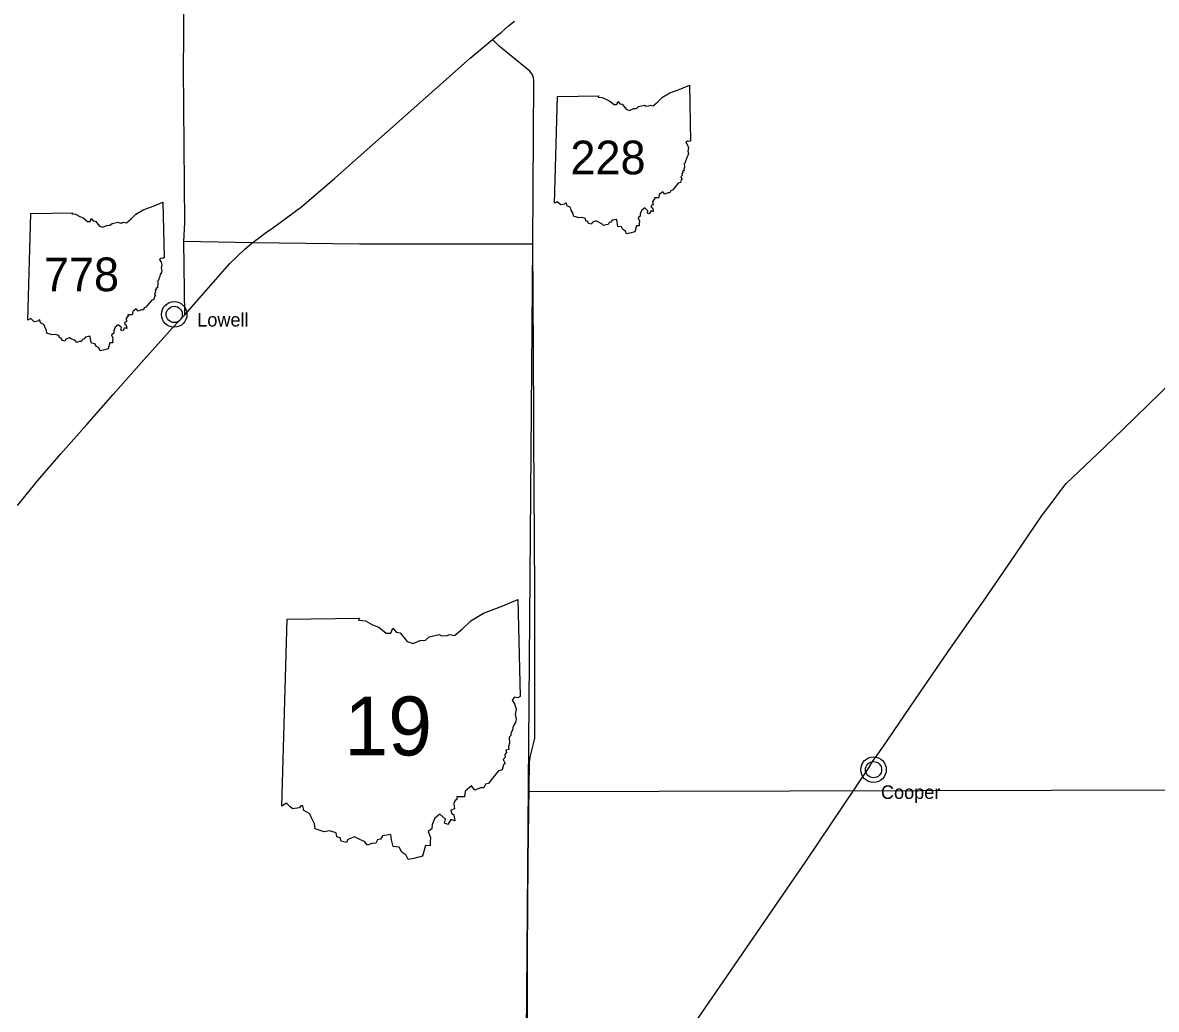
# Model space of a CAD drawing. Extents: x 0 to 882, y 0 to 440.
# Drawn here: x 381 to 468.1, y 237.6 to 313.4 of the extents above; entities that cross this region are included whole.
import ezdxf

# ---------------------------------------------------------------- set-up
doc = ezdxf.new("R2010")
doc.units = 0
for name, color, linetype in [('DV_X_Corp_Line', 7, 'Continuous'), ('GM_X_State_Route', 7, 'Continuous'), ('PV_P_Text', 7, 'Continuous'), ('RD_P_Fence', 7, 'Continuous'), ('SH_Data', 7, 'Continuous')]:
    doc.layers.add(name, color=color, linetype=linetype)

msp = doc.modelspace()

# ---------------------------------------------------------------- linework, layer by layer
at = {"layer": 'DV_X_Corp_Line'}
for centre, radius in [((392.644, 290.982), 0.982), ((392.644, 290.982), 0.623), ((446.38, 256.002), 0.982), ((446.38, 256.002), 0.623)]:
    msp.add_circle(centre, radius, dxfattribs=at)
at = {"layer": 'GM_X_State_Route'}
for points in [[(393.388, 296.583), (393.45, 298.02), (393.358, 309.898), (393.373, 312.282), (393.407, 316.485), (393.437, 322.641), (393.442, 323.16), (393.435, 323.568), (393.418, 329.26), (393.416, 329.793), (393.427, 329.817), (393.429, 329.823)], [(380.594, 276.297), (382.177, 278.219), (383.927, 280.267), (385.929, 282.534), (387.961, 284.83), (390.302, 287.496), (392.516, 289.957), (393.451, 290.953), (396.929, 294.898), (398.065, 296.003), (398.64, 296.481), (399.2, 296.898), (399.758, 297.317), (400.184, 297.613), (402.445, 299.276), (404.992, 301.46), (406.789, 303.043), (412.646, 308.25), (415.387, 310.662), (417.112, 312.1), (417.456, 312.406), (417.755, 312.634), (418.337, 313.152), (418.789, 313.518)], [(420.189, 296.375), (420.264, 308.966), (420.258, 309.159), (420.174, 309.385), (419.979, 309.671), (417.622, 311.587), (417.375, 311.828), (417.112, 312.1)], [(420.189, 296.375), (406.87, 296.372), (398.64, 296.481), (393.388, 296.583)], [(393.451, 290.953), (393.388, 296.583)], [(420.244, 288.037), (420.244, 288.063), (420.189, 296.375)], [(420.287, 281.563), (420.287, 281.596), (420.277, 283.008), (420.244, 288.037)], [(423.359, 222.836), (427.539, 229.077), (432.091, 235.746), (433.123, 237.244), (441.18, 248.941), (446.03, 256.151), (446.362, 256.695), (446.656, 257.106), (447.133, 257.815), (449.995, 261.974), (452.053, 265.013), (454.264, 268.16), (454.833, 268.957), (457.293, 272.533), (459.339, 275.545), (460.095, 276.557), (460.596, 277.229), (461.169, 277.995), (463.596, 280.26), (465.537, 282.134), (471.405, 287.839)], [(420.36, 269.737), (420.287, 281.563)], [(419.612, 222.364), (419.763, 229.03), (419.793, 241.9), (419.851, 249.025), (419.955, 256.517), (419.996, 256.959), (420.244, 257.98), (420.365, 258.414), (420.36, 269.737)]]:
    msp.add_lwpolyline(points, dxfattribs=at)
at = {"layer": 'PV_P_Text'}
for p, q in [((421.864, 299.522), (422.094, 307.729)), ((421.864, 299.522), (422.094, 307.729)), ((381.406, 290.538), (381.636, 298.746)), ((381.406, 290.538), (381.636, 298.746)), ((400.919, 253.198), (401.321, 267.56)), ((400.919, 253.198), (401.321, 267.56))]:
    msp.add_line(p, q, dxfattribs=at)
for points in [[(422.094, 307.729), (425.278, 307.782), (425.228, 307.683), (425.529, 307.662), (425.848, 307.487), (426.118, 307.376), (426.448, 307.115), (426.646, 307.118), (426.729, 307.332), (426.88, 307.167), (427.06, 307.138), (427.37, 306.745), (427.627, 306.66), (427.934, 306.794), (428.163, 306.816), (428.331, 306.95), (428.768, 307.063), (428.889, 306.995), (429.121, 307.009), (429.237, 307.059), (429.439, 307.014), (429.794, 307.313), (430.16, 307.665), (430.722, 307.997), (431.562, 308.311), (432.227, 308.592), (432.323, 304.333)], [(422.094, 307.729), (425.278, 307.782), (425.228, 307.683), (425.529, 307.662), (425.848, 307.487), (426.118, 307.376), (426.448, 307.115), (426.646, 307.118), (426.729, 307.332), (426.88, 307.167), (427.06, 307.138), (427.37, 306.745), (427.627, 306.66), (427.934, 306.794), (428.163, 306.816), (428.331, 306.95), (428.768, 307.063), (428.889, 306.995), (429.121, 307.009), (429.237, 307.059), (429.439, 307.014), (429.794, 307.313), (430.16, 307.665), (430.722, 307.997), (431.562, 308.311), (432.227, 308.592), (432.323, 304.333)], [(432.323, 304.333), (432.224, 304.274), (432.072, 304.302), (431.969, 304.182), (432.096, 303.983), (432.156, 303.772), (432.103, 303.54), (432.155, 303.349), (432.12, 303.189), (432.024, 303.029), (431.991, 302.877), (431.909, 302.717), (431.916, 302.627), (431.838, 302.556), (431.852, 302.29), (431.813, 302.142), (431.827, 302.015), (431.7, 301.982), (431.729, 301.876), (431.649, 301.795), (431.666, 301.655), (431.575, 301.566), (431.664, 301.387), (431.593, 301.331), (431.534, 301.113), (431.372, 301.069), (431.048, 300.672), (430.934, 300.522), (430.806, 300.484), (430.735, 300.33), (430.577, 300.329), (430.338, 300.222), (430.183, 300.406), (429.912, 300.185), (429.881, 299.929), (429.538, 299.937), (429.552, 299.808), (429.475, 299.77), (429.406, 299.64), (429.446, 299.41), (429.286, 299.351), (429.305, 299.218), (429.408, 299.136), (429.454, 298.88), (429.283, 298.932), (429.143, 298.717), (429, 298.767), (429.047, 298.95), (428.804, 299.169), (428.575, 298.993), (428.455, 298.713), (428.454, 298.524), (428.283, 298.409), (428.392, 298.143), (428.372, 297.959), (428.376, 297.784), (428.162, 297.79), (428.032, 297.319)], [(432.323, 304.333), (432.224, 304.274), (432.072, 304.302), (431.969, 304.182), (432.096, 303.983), (432.156, 303.772), (432.103, 303.54), (432.155, 303.349), (432.12, 303.189), (432.024, 303.029), (431.991, 302.877), (431.909, 302.717), (431.916, 302.627), (431.838, 302.556), (431.852, 302.29), (431.813, 302.142), (431.827, 302.015), (431.7, 301.982), (431.729, 301.876), (431.649, 301.795), (431.666, 301.655), (431.575, 301.566), (431.664, 301.387), (431.593, 301.331), (431.534, 301.113), (431.372, 301.069), (431.048, 300.672), (430.934, 300.522), (430.806, 300.484), (430.735, 300.33), (430.577, 300.329), (430.338, 300.222), (430.183, 300.406), (429.912, 300.185), (429.881, 299.929), (429.538, 299.937), (429.552, 299.808), (429.475, 299.77), (429.406, 299.64), (429.446, 299.41), (429.286, 299.351), (429.305, 299.218), (429.408, 299.136), (429.454, 298.88), (429.283, 298.932), (429.143, 298.717), (429, 298.767), (429.047, 298.95), (428.804, 299.169), (428.575, 298.993), (428.455, 298.713), (428.454, 298.524), (428.283, 298.409), (428.392, 298.143), (428.372, 297.959), (428.376, 297.784), (428.162, 297.79), (428.032, 297.319)], [(381.636, 298.746), (384.82, 298.799), (384.77, 298.7), (385.071, 298.679), (385.39, 298.504), (385.66, 298.393), (385.99, 298.132), (386.188, 298.135), (386.271, 298.349), (386.422, 298.184), (386.602, 298.154), (386.912, 297.762), (387.169, 297.676), (387.476, 297.811), (387.705, 297.833), (387.873, 297.966), (388.31, 298.08), (388.432, 298.012), (388.663, 298.026), (388.779, 298.076), (388.981, 298.031), (389.336, 298.329), (389.702, 298.681), (390.264, 299.013), (391.104, 299.328), (391.769, 299.609), (391.865, 295.35)], [(381.636, 298.746), (384.82, 298.799), (384.77, 298.7), (385.071, 298.679), (385.39, 298.504), (385.66, 298.393), (385.99, 298.132), (386.188, 298.135), (386.271, 298.349), (386.422, 298.184), (386.602, 298.154), (386.912, 297.762), (387.169, 297.676), (387.476, 297.811), (387.705, 297.833), (387.873, 297.966), (388.31, 298.08), (388.432, 298.012), (388.663, 298.026), (388.779, 298.076), (388.981, 298.031), (389.336, 298.329), (389.702, 298.681), (390.264, 299.013), (391.104, 299.328), (391.769, 299.609), (391.865, 295.35)], [(428.032, 297.319), (427.661, 297.229), (427.403, 297.175), (427.312, 297.389), (427.127, 297.502), (427.007, 297.718), (426.742, 297.747), (426.68, 298.043), (426.65, 298.283), (426.288, 298.224), (426.188, 298.077), (426.06, 298.037), (425.985, 297.889), (425.81, 297.877), (425.623, 297.807), (425.5, 297.952), (425.192, 298.098), (425.053, 298.173), (424.764, 298.057), (424.702, 297.918), (424.472, 297.979), (424.418, 298.133), (424.278, 298.18), (424.248, 298.343), (423.95, 298.43), (423.722, 298.396), (423.32, 298.527), (423.295, 298.742), (423.158, 299.004), (423.087, 299.186), (422.833, 299.325), (422.781, 299.542), (422.7, 299.535), (422.626, 299.447), (422.344, 299.407), (422.231, 299.496), (422.073, 299.646), (421.864, 299.522)], [(428.032, 297.319), (427.661, 297.229), (427.403, 297.175), (427.312, 297.389), (427.127, 297.502), (427.007, 297.718), (426.742, 297.747), (426.68, 298.043), (426.65, 298.283), (426.288, 298.224), (426.188, 298.077), (426.06, 298.037), (425.985, 297.889), (425.81, 297.877), (425.623, 297.807), (425.5, 297.952), (425.192, 298.098), (425.053, 298.173), (424.764, 298.057), (424.702, 297.918), (424.472, 297.979), (424.418, 298.133), (424.278, 298.18), (424.248, 298.343), (423.95, 298.43), (423.722, 298.396), (423.32, 298.527), (423.295, 298.742), (423.158, 299.004), (423.087, 299.186), (422.833, 299.325), (422.781, 299.542), (422.7, 299.535), (422.626, 299.447), (422.344, 299.407), (422.231, 299.496), (422.073, 299.646), (421.864, 299.522)], [(391.865, 295.35), (391.767, 295.29), (391.614, 295.318), (391.511, 295.199), (391.638, 295), (391.698, 294.789), (391.645, 294.557), (391.698, 294.366), (391.662, 294.205), (391.566, 294.046), (391.533, 293.894), (391.451, 293.734), (391.458, 293.644), (391.38, 293.573), (391.394, 293.307), (391.355, 293.159), (391.369, 293.032), (391.243, 292.998), (391.271, 292.893), (391.191, 292.812), (391.208, 292.672), (391.117, 292.583), (391.206, 292.404), (391.135, 292.348), (391.076, 292.13), (390.914, 292.086), (390.59, 291.689), (390.476, 291.539), (390.348, 291.501), (390.277, 291.347), (390.119, 291.346), (389.88, 291.239), (389.725, 291.423), (389.454, 291.202), (389.423, 290.946), (389.08, 290.954), (389.094, 290.825), (389.017, 290.787), (388.948, 290.657), (388.988, 290.427), (388.828, 290.368), (388.847, 290.234), (388.95, 290.153), (388.996, 289.897), (388.825, 289.949), (388.685, 289.734), (388.542, 289.784), (388.589, 289.967), (388.346, 290.186), (388.117, 290.01), (387.997, 289.729), (387.996, 289.54), (387.825, 289.426), (387.934, 289.159), (387.914, 288.976), (387.918, 288.801), (387.704, 288.807), (387.574, 288.336)], [(391.865, 295.35), (391.767, 295.29), (391.614, 295.318), (391.511, 295.199), (391.638, 295), (391.698, 294.789), (391.645, 294.557), (391.698, 294.366), (391.662, 294.205), (391.566, 294.046), (391.533, 293.894), (391.451, 293.734), (391.458, 293.644), (391.38, 293.573), (391.394, 293.307), (391.355, 293.159), (391.369, 293.032), (391.243, 292.998), (391.271, 292.893), (391.191, 292.812), (391.208, 292.672), (391.117, 292.583), (391.206, 292.404), (391.135, 292.348), (391.076, 292.13), (390.914, 292.086), (390.59, 291.689), (390.476, 291.539), (390.348, 291.501), (390.277, 291.347), (390.119, 291.346), (389.88, 291.239), (389.725, 291.423), (389.454, 291.202), (389.423, 290.946), (389.08, 290.954), (389.094, 290.825), (389.017, 290.787), (388.948, 290.657), (388.988, 290.427), (388.828, 290.368), (388.847, 290.234), (388.95, 290.153), (388.996, 289.897), (388.825, 289.949), (388.685, 289.734), (388.542, 289.784), (388.589, 289.967), (388.346, 290.186), (388.117, 290.01), (387.997, 289.729), (387.996, 289.54), (387.825, 289.426), (387.934, 289.159), (387.914, 288.976), (387.918, 288.801), (387.704, 288.807), (387.574, 288.336)], [(387.574, 288.336), (387.203, 288.246), (386.945, 288.192), (386.854, 288.406), (386.669, 288.519), (386.549, 288.734), (386.284, 288.764), (386.222, 289.06), (386.192, 289.3), (385.83, 289.24), (385.731, 289.094), (385.602, 289.054), (385.528, 288.906), (385.352, 288.894), (385.165, 288.824), (385.042, 288.969), (384.734, 289.115), (384.595, 289.19), (384.306, 289.073), (384.244, 288.935), (384.014, 288.996), (383.96, 289.15), (383.82, 289.196), (383.79, 289.36), (383.492, 289.447), (383.264, 289.412), (382.862, 289.544), (382.837, 289.759), (382.7, 290.021), (382.629, 290.203), (382.375, 290.342), (382.323, 290.558), (382.242, 290.552), (382.168, 290.464), (381.886, 290.424), (381.773, 290.512), (381.615, 290.663), (381.406, 290.538)], [(387.574, 288.336), (387.203, 288.246), (386.945, 288.192), (386.854, 288.406), (386.669, 288.519), (386.549, 288.734), (386.284, 288.764), (386.222, 289.06), (386.192, 289.3), (385.83, 289.24), (385.731, 289.094), (385.602, 289.054), (385.528, 288.906), (385.352, 288.894), (385.165, 288.824), (385.042, 288.969), (384.734, 289.115), (384.595, 289.19), (384.306, 289.073), (384.244, 288.935), (384.014, 288.996), (383.96, 289.15), (383.82, 289.196), (383.79, 289.36), (383.492, 289.447), (383.264, 289.412), (382.862, 289.544), (382.837, 289.759), (382.7, 290.021), (382.629, 290.203), (382.375, 290.342), (382.323, 290.558), (382.242, 290.552), (382.168, 290.464), (381.886, 290.424), (381.773, 290.512), (381.615, 290.663), (381.406, 290.538)], [(401.321, 267.56), (406.893, 267.654), (406.806, 267.48), (407.332, 267.444), (407.891, 267.137), (408.363, 266.944), (408.941, 266.487), (409.287, 266.492), (409.433, 266.866), (409.698, 266.577), (410.012, 266.526), (410.555, 265.838), (411.004, 265.689), (411.541, 265.925), (411.942, 265.964), (412.236, 266.197), (413, 266.396), (413.214, 266.276), (413.618, 266.3), (413.822, 266.389), (414.175, 266.31), (414.797, 266.832), (415.437, 267.448), (416.421, 268.029), (417.891, 268.579), (419.053, 269.072), (419.221, 261.618)], [(401.321, 267.56), (406.893, 267.654), (406.806, 267.48), (407.332, 267.444), (407.891, 267.137), (408.363, 266.944), (408.941, 266.487), (409.287, 266.492), (409.433, 266.866), (409.698, 266.577), (410.012, 266.526), (410.555, 265.838), (411.004, 265.689), (411.541, 265.925), (411.942, 265.964), (412.236, 266.197), (413, 266.396), (413.214, 266.276), (413.618, 266.3), (413.822, 266.389), (414.175, 266.31), (414.797, 266.832), (415.437, 267.448), (416.421, 268.029), (417.891, 268.579), (419.053, 269.072), (419.221, 261.618)], [(419.221, 261.618), (419.05, 261.514), (418.783, 261.563), (418.603, 261.354), (418.825, 261.005), (418.93, 260.637), (418.837, 260.23), (418.929, 259.895), (418.867, 259.615), (418.699, 259.336), (418.641, 259.07), (418.498, 258.79), (418.51, 258.633), (418.374, 258.509), (418.399, 258.042), (418.33, 257.784), (418.353, 257.561), (418.133, 257.503), (418.183, 257.319), (418.043, 257.177), (418.073, 256.932), (417.914, 256.776), (418.068, 256.463), (417.944, 256.364), (417.841, 255.984), (417.558, 255.906), (416.992, 255.211), (416.792, 254.948), (416.567, 254.882), (416.443, 254.612), (416.167, 254.611), (415.748, 254.424), (415.477, 254.746), (415.003, 254.358), (414.949, 253.911), (414.349, 253.925), (414.373, 253.699), (414.239, 253.633), (414.117, 253.406), (414.188, 253.003), (413.907, 252.9), (413.941, 252.666), (414.121, 252.523), (414.201, 252.076), (413.902, 252.166), (413.658, 251.789), (413.407, 251.878), (413.489, 252.197), (413.065, 252.581), (412.663, 252.273), (412.453, 251.782), (412.451, 251.451), (412.152, 251.252), (412.344, 250.784), (412.309, 250.463), (412.314, 250.157), (411.94, 250.168), (411.714, 249.343)], [(419.221, 261.618), (419.05, 261.514), (418.783, 261.563), (418.603, 261.354), (418.825, 261.005), (418.93, 260.637), (418.837, 260.23), (418.929, 259.895), (418.867, 259.615), (418.699, 259.336), (418.641, 259.07), (418.498, 258.79), (418.51, 258.633), (418.374, 258.509), (418.399, 258.042), (418.33, 257.784), (418.353, 257.561), (418.133, 257.503), (418.183, 257.319), (418.043, 257.177), (418.073, 256.932), (417.914, 256.776), (418.068, 256.463), (417.944, 256.364), (417.841, 255.984), (417.558, 255.906), (416.992, 255.211), (416.792, 254.948), (416.567, 254.882), (416.443, 254.612), (416.167, 254.611), (415.748, 254.424), (415.477, 254.746), (415.003, 254.358), (414.949, 253.911), (414.349, 253.925), (414.373, 253.699), (414.239, 253.633), (414.117, 253.406), (414.188, 253.003), (413.907, 252.9), (413.941, 252.666), (414.121, 252.523), (414.201, 252.076), (413.902, 252.166), (413.658, 251.789), (413.407, 251.878), (413.489, 252.197), (413.065, 252.581), (412.663, 252.273), (412.453, 251.782), (412.451, 251.451), (412.152, 251.252), (412.344, 250.784), (412.309, 250.463), (412.314, 250.157), (411.94, 250.168), (411.714, 249.343)], [(411.714, 249.343), (411.063, 249.186), (410.612, 249.091), (410.453, 249.466), (410.13, 249.663), (409.92, 250.041), (409.456, 250.092), (409.347, 250.61), (409.295, 251.03), (408.661, 250.926), (408.487, 250.669), (408.262, 250.6), (408.132, 250.342), (407.825, 250.32), (407.496, 250.198), (407.281, 250.452), (406.742, 250.707), (406.5, 250.838), (405.994, 250.634), (405.886, 250.392), (405.483, 250.499), (405.388, 250.768), (405.144, 250.849), (405.09, 251.135), (404.569, 251.288), (404.17, 251.227), (403.467, 251.457), (403.424, 251.834), (403.184, 252.292), (403.059, 252.611), (402.614, 252.854), (402.524, 253.233), (402.382, 253.221), (402.252, 253.068), (401.758, 252.997), (401.561, 253.152), (401.284, 253.416), (400.919, 253.198)], [(411.714, 249.343), (411.063, 249.186), (410.612, 249.091), (410.453, 249.466), (410.13, 249.663), (409.92, 250.041), (409.456, 250.092), (409.347, 250.61), (409.295, 251.03), (408.661, 250.926), (408.487, 250.669), (408.262, 250.6), (408.132, 250.342), (407.825, 250.32), (407.496, 250.198), (407.281, 250.452), (406.742, 250.707), (406.5, 250.838), (405.994, 250.634), (405.886, 250.392), (405.483, 250.499), (405.388, 250.768), (405.144, 250.849), (405.09, 251.135), (404.569, 251.288), (404.17, 251.227), (403.467, 251.457), (403.424, 251.834), (403.184, 252.292), (403.059, 252.611), (402.614, 252.854), (402.524, 253.233), (402.382, 253.221), (402.252, 253.068), (401.758, 252.997), (401.561, 253.152), (401.284, 253.416), (400.919, 253.198)]]:
    msp.add_lwpolyline(points, dxfattribs=at)
at = {"layer": 'RD_P_Fence'}
msp.add_line((419.612, 222.364), (420.189, 296.375), dxfattribs=at)
at = {"layer": 'SH_Data'}
msp.add_line((548.986, 254.627), (419.861, 254.303), dxfattribs=at)

# ---------------------------------------------------------------- texts
at = {"layer": 'DV_X_Corp_Line'}
for s, p in [('Lowell', (394.412, 290.052)), ('Cooper', (446.946, 253.752))]:
    msp.add_text(s, height=1.0417, rotation=0.00001, dxfattribs=at).set_placement(p)
at = {"layer": 'PV_P_Text'}
for s, height, p in [('228', 2.5875, (423.088, 301.748)), ('778', 2.5875, (382.63, 292.765)), ('19', 4.5281, (405.718, 257.094))]:
    msp.add_text(s, height=height, dxfattribs=at).set_placement(p)

doc.saveas('drawing.dxf')
